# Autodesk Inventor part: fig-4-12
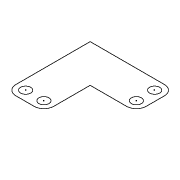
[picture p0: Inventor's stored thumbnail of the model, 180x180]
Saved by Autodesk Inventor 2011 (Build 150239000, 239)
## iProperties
Created: 2005-02
Part Number: fig-4-12
Document SubType Name: Modeling
Designer: CADCIM
Manufacturer: Standard
Standards Organization: Custom
Density: 1 g/cm^3
Author: CADCIM
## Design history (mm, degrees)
sketch "Sketch1"
  geometry: L1 (5.141, 24.979)-(-32.827, 24.979); L2 (-32.827, 24.979)-(-32.827, -12.989); L3 (-27.827, -17.989)-(-18.492, -17.989); L4 (-13.492, -12.989)-(-13.492, 5.644); L5 (-13.492, 5.644)-(5.141, 5.644); L6 (10.141, 10.644)-(10.141, 19.979); C1 r 2.58 at (-27.827, -12.989); C2 r 2.58 at (-18.492, -12.989); C3 r 2.58 at (5.141, 10.644); C4 r 2.58 at (5.141, 19.979); A1 r 5 centre (-27.827, -12.989) between (-32.827, -12.989) and (-27.827, -17.989); A2 r 5 centre (-18.492, -12.989) between (-18.492, -17.989) and (-13.492, -12.989); A3 r 5 centre (5.141, 10.644) between (5.141, 5.644) and (10.141, 10.644); A4 r 5 centre (5.141, 19.979) between (10.141, 19.979) and (5.141, 24.979)
  constraints: 12 end point, 8 centre point, 8 point on circle, 8 tangent, 4 equal radius, 4 parallel, 3 perpendicular, 2 coincident, 1 horizontal
